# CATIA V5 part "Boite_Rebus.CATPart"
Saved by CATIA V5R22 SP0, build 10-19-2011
Part number: Boite_Rebus
Bounding box of the stored display mesh (mm): x -130 to 130, y -80 to 80, z 0 to 70
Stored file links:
  U:\S9A\PER\CAO\Assemblage\Boite_Rebus.CATPart
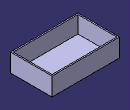
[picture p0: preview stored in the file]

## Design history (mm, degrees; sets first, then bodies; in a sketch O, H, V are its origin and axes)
Body1 (main body)
  Sketch1 on xy-plane, origin (0, 0, 0), H (1, 0, 0), V (0, 1, 0)
    point P1 (-130, 80)
    line L1 (-130, 80) -> (130, 80)
    line L2 (130, 80) -> (130, -80)
    line L3 (130, -80) -> (-130, -80)
    line L4 (-130, -80) -> (-130, 80)
    point P2 (130, 80)
    point P3 (130, -80)
    point P4 (-130, -80)
    length L1 = 260
    length L2 = 160
    horizontal: L1 H, L3 H
    vertical: L2 V, L4 V
    equidistance: P3 P1 O, P2 P4 O
  Pad1: profile Sketch1, direction (0, 0, 1), length 70
  Shell1: ExtOffset 0, Face end face of Pad1, IntOffset 5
